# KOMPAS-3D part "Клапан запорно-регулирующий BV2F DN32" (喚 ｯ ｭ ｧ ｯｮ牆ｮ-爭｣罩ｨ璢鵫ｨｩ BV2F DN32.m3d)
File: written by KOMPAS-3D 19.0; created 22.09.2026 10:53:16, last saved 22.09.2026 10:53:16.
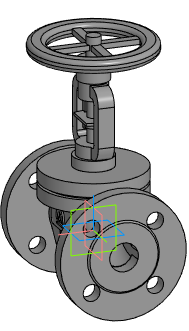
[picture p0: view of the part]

Document properties: Автор: Энергия; Полное имя файла: Z:\3.Личные\sachek\Dendor\_3D для проектировщиков\5.7 Клапан запорно-регулирующий BV2F\BV2F_STP\Клапан запорно-регулирующий BV2F DN32.m3d

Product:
- Part/product: Клапан запорно-регулирующий BV2F DN32

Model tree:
1. Операция без истории:1  (labels: Клапан запорно-регулирующий BV2F DN32)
